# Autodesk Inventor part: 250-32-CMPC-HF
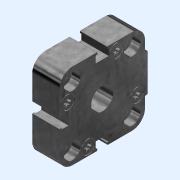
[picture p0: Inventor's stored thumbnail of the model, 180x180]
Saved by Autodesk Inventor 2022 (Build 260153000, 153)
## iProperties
Category: PARTsolutions
Company: METALWORK
Part Number: 250-32-CMPC-HF
Material: Generico
Catalog Web Link: www.cadenas.de
Description: CMPC-HF-
Vendor: METALWORK
Document SubType Name: Modeling
Designer: partserver
Manufacturer: METALWORK
Mass: 25.385 g
Surface Area: 95.1722 cm^2
Volume: 25.385 cm^3
Density: 1 g/cm^3
Appearance: Acciaio galvanizzato
PSOL_IDENT_0: {$CADENAS_DATA\23d-libs\metalwork\actuators\comp_cyl_ser_cmpc\parts\cmpc_head_front.prj},180 {VTYP=3
PSOL_IDENT_1: D},{NB=250-32-CMPC-HF},{LINA=250-32-CMPC-HF},{NN=CMPC-HF},{DATE=18.06.2021 08:06:07},{GEOMDATE=16.03
PSOL_IDENT_2: .2016 08:40:06},{VERSION=},{LINEID=50},{WBVAR=TYPE,VE},{WBNUMERIC=TYPE}  {NB=250-32-CMPC-HF},{LINA=2
PSOL_IDENT_3: 50-32-CMPC-HF},{KT=DUMMY},{IDNR=},{DI=32},{TYPE=25},{TX= 23,'Centre distance to UNITOP, male rod', 2
PSOL_IDENT_4: 4,'Centre distance to UNITOP, female rod', 25,'Centre distance to ISO, male rod', 26,'Centre distanc
PSOL_IDENT_5: e to ISO, female rod' },{VE=0},{VX='0','Double-acting','1','Double-acting, through-rod','2','Double-
PSOL_IDENT_6: acting, perfored through-rod','3','Single-acting, retracted rod','4','Single-acting, extended rod','
PSOL_IDENT_7: 5','Single acting, through-rod','6','Single-acting, perfored through-rod','A','Double-acting, throug
PSOL_IDENT_8: h-rod, non-rotating'},{A=46.300},{B=32.5},{BB=32.250},{B2=0.000},{C=12.000},{D=47.800},{D1=9.000},{D
PSOL_IDENT_9: 2=7.600},{D3=7.000},{R1=7.150},{H=7.500},{H1=6.950},{H2=5.400},{H3=14.750},{H4=2.800},{L=4.500},{LD=
PSOL_IDENT_10: 1.700},{L1=3.700},{L2=1.200},{L3=10.000},{O=6.000},{Q=9.728},{SW=0.000},{X=18.700},{Y=7.700},{R2=3.4
PSOL_IDENT_11: 00},{R3=0.300},{R4=0.500},{C1=8.500}
NB: 250-32-CMPC-HF
NN: CMPC-HF
NBSYN: $TYPE.$VE.-$DI.-CMPC-HF
LINA: 250-32-CMPC-HF
CATALOG: Metalwork
DI: 32
TYPE: Centre distance to ISO, male rod
VE: Double-acting
A: 46.3
B: 32.5
BB: 32.25
B2: 0
C: 12
D: 47.8
D2: 7.6
D3: 7
R1: 7.15
H: 7.5
H1: 6.95
H2: 5.4
H3: 14.75
H4: 2.8
LD: 1.7
L1: 3.7
L2: 1.2
L3: 10
O: 6
Q: 9.728
SW: 0
X: 18.7
Y: 7.7
R2: 3.4
R3: 0.3
R4: 0.5
C1: 8.5
SUPPLIER: METALWORK
ARTICLENO: 250-32-CMPC-HF
BOMINFO: 250-32-CMPC-HF
CREATOR: CADENAS GmbH
Title: 250-32-CMPC-HF
Author: Cadenas PARTsolutions
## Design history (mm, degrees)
sketch "Sketch_1"
  geometry: L1 (-23.15, 16)-(-23.15, 3.1); L2 (-22.75, 2.7)-(-22.15, 2.7); L3 (-21.95, 2.9)-(-21.95, 3.275); L4 (-21.75, 3.475)-(-18.45, 3.475); L5 (-18.25, 3.275)-(-18.25, -3.275); L6 (-18.45, -3.475)-(-21.75, -3.475); L7 (-21.95, -3.275)-(-21.95, -2.9); L8 (-22.15, -2.7)-(-22.75, -2.7); L9 (-23.15, -3.1)-(-23.15, -16); L10 (-16, -23.15)-(-3.1, -23.15); L11 (-2.7, -22.75)-(-2.7, -22.15); L12 (-2.9, -21.95)-(-3.275, -21.95); L13 (-3.475, -21.75)-(-3.475, -18.45); L14 (-3.275, -18.25)-(3.275, -18.25); L15 (3.475, -18.45)-(3.475, -21.75); L16 (3.275, -21.95)-(2.9, -21.95); L17 (2.7, -22.15)-(2.7, -22.75); L18 (3.1, -23.15)-(16, -23.15); L19 (23.15, -16)-(23.15, -10.402); L20 (23.15, -10.402)-(24.65, -10); L21 (24.65, -10)-(24.65, 10); L22 (24.65, 10)-(23.15, 10.402); L23 (23.15, 10.402)-(23.15, 16); L24 (16, 23.15)-(3.1, 23.15); L25 (2.7, 22.75)-(2.7, 22.15); L26 (2.9, 21.95)-(3.275, 21.95); L27 (3.475, 21.75)-(3.475, 18.45); L28 (3.275, 18.25)-(-3.275, 18.25); L29 (-3.475, 18.45)-(-3.475, 21.75); L30 (-3.275, 21.95)-(-2.9, 21.95); L31 (-2.7, 22.15)-(-2.7, 22.75); L32 (-3.1, 23.15)-(-16, 23.15); C1 r 6 at (0, 0); A1 r 7.15 centre (-16, 16) between (-16, 23.15) and (-23.15, 16); A2 r 0.4 centre (-22.75, 3.1) between (-23.15, 3.1) and (-22.75, 2.7); A3 r 0.2 centre (-22.15, 2.9) between (-22.15, 2.7) and (-21.95, 2.9); A4 r 0.2 centre (-21.75, 3.275) between (-21.75, 3.475) and (-21.95, 3.275); A5 r 0.2 centre (-18.45, 3.275) between (-18.25, 3.275) and (-18.45, 3.475); A6 r 0.2 centre (-18.45, -3.275) between (-18.45, -3.475) and (-18.25, -3.275); A7 r 0.2 centre (-21.75, -3.275) between (-21.95, -3.275) and (-21.75, -3.475); A8 r 0.2 centre (-22.15, -2.9) between (-21.95, -2.9) and (-22.15, -2.7); A9 r 0.4 centre (-22.75, -3.1) between (-22.75, -2.7) and (-23.15, -3.1); A10 r 7.15 centre (-16, -16) between (-23.15, -16) and (-16, -23.15); A11 r 0.4 centre (-3.1, -22.75) between (-3.1, -23.15) and (-2.7, -22.75); A12 r 0.2 centre (-2.9, -22.15) between (-2.7, -22.15) and (-2.9, -21.95); A13 r 0.2 centre (-3.275, -21.75) between (-3.475, -21.75) and (-3.275, -21.95); A14 r 0.2 centre (-3.275, -18.45) between (-3.275, -18.25) and (-3.475, -18.45); A15 r 0.2 centre (3.275, -18.45) between (3.475, -18.45) and (3.275, -18.25); A16 r 0.2 centre (3.275, -21.75) between (3.275, -21.95) and (3.475, -21.75); A17 r 0.2 centre (2.9, -22.15) between (2.9, -21.95) and (2.7, -22.15); A18 r 0.4 centre (3.1, -22.75) between (2.7, -22.75) and (3.1, -23.15); A19 r 7.15 centre (16, -16) between (16, -23.15) and (23.15, -16); A20 r 7.15 centre (16, 16) between (23.15, 16) and (16, 23.15); A21 r 0.4 centre (3.1, 22.75) between (3.1, 23.15) and (2.7, 22.75); A22 r 0.2 centre (2.9, 22.15) between (2.7, 22.15) and (2.9, 21.95); A23 r 0.2 centre (3.275, 21.75) between (3.475, 21.75) and (3.275, 21.95); A24 r 0.2 centre (3.275, 18.45) between (3.275, 18.25) and (3.475, 18.45); A25 r 0.2 centre (-3.275, 18.45) between (-3.475, 18.45) and (-3.275, 18.25); A26 r 0.2 centre (-3.275, 21.75) between (-3.275, 21.95) and (-3.475, 21.75); A27 r 0.2 centre (-2.9, 22.15) between (-2.9, 21.95) and (-2.7, 22.15); A28 r 0.4 centre (-3.1, 22.75) between (-2.7, 22.75) and (-3.1, 23.15); 1 further point
  constraints: 64 end point, 56 point on circle, 29 centre point
extrude "Extrusion1" join sketch "Sketch_1" distance "d0" = 14.75; taper "d1" = 0 deg
sketch "Sketch2"
  geometry: 1 further point
hole "Hole1" sketch "Sketch2" at (7.5, 10) diameter "d2" = 8.566; stored, may be unused: countersink angle "d6" = 90 deg, drill point angle "d8" = 120 deg; dims "d3" = 9.728, "d4" = 4, "d5" = 2, "d7" = 14.592
sketch "Sketch_7"
  geometry: L1 (14.75, -16.25)-(0, -16.25); L2 (0, -16.25)-(0, -11.75); L3 (0, -11.75)-(4.5, -11.75); L4 (4.5, -11.75)-(4.5, -13.792); L5 (4.5, -13.792)-(14.75, -13.792); L6 (14.75, -13.792)-(14.75, -16.25); L7 (14.75, -16.25)-(0, -16.25)
  constraints: 14 end point
revolve "Revolution1" sketch "Sketch_7" stored, may be unused: angle "d9" = 360 deg
thread "Thread1" dims "d10" = 10.25, "d11" = 0
sketch "Sketch_10"
  geometry: L1 (14.75, 16.25)-(0, 16.25); L2 (0, 16.25)-(0, 20.75); L3 (0, 20.75)-(4.5, 20.75); L4 (4.5, 20.75)-(4.5, 18.709); L5 (4.5, 18.709)-(14.75, 18.709); L6 (14.75, 18.709)-(14.75, 16.25); L7 (14.75, 16.25)-(0, 16.25)
  constraints: 14 end point
revolve "Revolution2" sketch "Sketch_10" stored, may be unused: angle "d12" = 360 deg
thread "Thread2" dims "d13" = 10.25, "d14" = 0
sketch "Sketch_38"
  geometry: L1 (14.75, 16.25)-(0, 16.25); L2 (0, 16.25)-(0, 20.75); L3 (0, 20.75)-(4.5, 20.75); L4 (4.5, 20.75)-(4.5, 18.709); L5 (4.5, 18.709)-(14.75, 18.709); L6 (14.75, 18.709)-(14.75, 16.25); L7 (14.75, 16.25)-(0, 16.25)
  constraints: 14 end point
revolve "Revolution3" sketch "Sketch_38" stored, may be unused: angle "d15" = 360 deg
thread "Thread3" dims "d16" = 10.25, "d17" = 0
sketch "Sketch_39"
  geometry: L1 (14.75, -16.25)-(0, -16.25); L2 (0, -16.25)-(0, -11.75); L3 (0, -11.75)-(4.5, -11.75); L4 (4.5, -11.75)-(4.5, -13.792); L5 (4.5, -13.792)-(14.75, -13.792); L6 (14.75, -13.792)-(14.75, -16.25); L7 (14.75, -16.25)-(0, -16.25)
  constraints: 14 end point
revolve "Revolution4" sketch "Sketch_39" stored, may be unused: angle "d18" = 360 deg
thread "Thread4" dims "d19" = 10.25, "d20" = 0
sketch "Sketch_13"
  geometry: C1 r 3.8 at (-7.7, 18.7); C2 r 3.5 at (-7.7, 18.7); 2 further points
  constraints: 2 centre point
extrude "Extrusion2" cut sketch "Sketch_13" distance "d21" = 2.8; taper "d22" = 0 deg
pattern_linear "Rectangular Pattern1" dims "d25" = 28.6, "d28" = 28.6
sketch "Sketch_19"
  geometry: L1 (-8.84, 20.095)-(-8.736, 19.706); L2 (-9.089, 19.094)-(-9.478, 18.99); L3 (-9.478, 18.41)-(-9.089, 18.306); L4 (-8.736, 17.694)-(-8.84, 17.305); L5 (-8.338, 17.016)-(-8.054, 17.3); L6 (-7.346, 17.3)-(-7.062, 17.016); L7 (-6.56, 17.305)-(-6.664, 17.694); L8 (-6.311, 18.306)-(-5.922, 18.41); L9 (-5.922, 18.99)-(-6.311, 19.094); L10 (-6.664, 19.706)-(-6.56, 20.095); L11 (-7.062, 20.384)-(-7.346, 20.1); L12 (-8.054, 20.1)-(-8.338, 20.384); A1 r 0.3 centre (-8.55, 20.172) between (-8.338, 20.384) and (-8.84, 20.095); A2 r 0.5 centre (-9.219, 19.577) between (-9.089, 19.094) and (-8.736, 19.706); A3 r 0.3 centre (-9.4, 18.7) between (-9.478, 18.99) and (-9.478, 18.41); A4 r 0.5 centre (-9.219, 17.823) between (-8.736, 17.694) and (-9.089, 18.306); A5 r 0.3 centre (-8.55, 17.228) between (-8.84, 17.305) and (-8.338, 17.016); A6 r 0.5 centre (-7.7, 16.946) between (-7.346, 17.3) and (-8.054, 17.3); A7 r 0.3 centre (-6.85, 17.228) between (-7.062, 17.016) and (-6.56, 17.305); A8 r 0.5 centre (-6.181, 17.823) between (-6.311, 18.306) and (-6.664, 17.694); A9 r 0.3 centre (-6, 18.7) between (-5.922, 18.41) and (-5.922, 18.99); A10 r 0.5 centre (-6.181, 19.577) between (-6.664, 19.706) and (-6.311, 19.094); A11 r 0.3 centre (-6.85, 20.172) between (-6.56, 20.095) and (-7.062, 20.384); A12 r 0.5 centre (-7.7, 20.454) between (-8.054, 20.1) and (-7.346, 20.1)
  constraints: 24 end point, 24 point on circle, 12 centre point
extrude "Extrusion3" cut sketch "Sketch_19" distance "d29" = 1.7; taper "d30" = 0 deg
pattern_linear "Rectangular Pattern2" dims "d33" = 28.6, "d36" = 28.6
node "accessories_XY"
node "accessories_YZ"
node "accessories_ZX"
node "accessories_X"
node "accessories_Y"
node "accessories_Z"
node "accessories_Center"
node "head_l_XY"
node "head_l_YZ"
node "head_l_ZX"
node "head_l_X"
node "head_l_Y"
node "head_l_Z"
node "head_l_Center"
node "rod_XY"
node "rod_YZ"
node "rod_ZX"
node "rod_X"
node "rod_Y"
node "rod_Z"
node "rod_Center"
body "Solid1"
other parameters: "d37" = 0, "d38" = 0, "d39" = 0
